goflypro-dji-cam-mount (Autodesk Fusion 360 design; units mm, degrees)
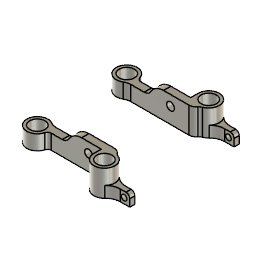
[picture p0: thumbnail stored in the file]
sketch "Skizze1" plane through (0, 0, 0) normal (0, 0, 1) x axis (1, 0, 0)
  line L1 (10, 0.85) -> (10, 2)
  line L2 (7.15, 0) -> (7.15, -2)
  line L3 (10, 2) -> (-7.9696, 2)
  line L4 (7.15, 0) -> (-7.15, 0)
  line L5 (-2, 0) -> (-2, 2)
  line L6 (8.5482, 0) -> (7.15, 0)
  line L7 (9.55, 0) -> (8.5482, 0)
  line L8 (10, 0.85) -> (10, 0.05)
  circle C1 centre (-10, 0) radius 2.05
  circle C2 centre (10, -2) radius 2.05
  circle C3 centre (-10, 0) radius 2.85
  circle C4 centre (10, -2) radius 2.85
  point P6 (7.15, -2)
  point P7 (10, 0.85)
  point P8 (-7.15, 0)
  point P9 (-7.9696, 2)
  point P12 (-2, 2)
  point P13 (-2, 0)
  point P15 (9.55, 0)
  point P16 (10, 0.05)
  concentric C1 C3
  coincident C4 P6
  tangent C4 L2
  coincident C4 P7
  perpendicular L1 L3
  perpendicular L2 L4
  coincident C3 P8
  coincident C3 P9
  coincident L3 P12
  coincident L4 P13
  perpendicular L4 L5
  perpendicular L2 L6
  parallel L6 L7
  perpendicular L7 L8
  coincident C2 P15
  coincident C2 P16
  dimension "d1" diameter C1 = 4.1
  dimension "d2" diameter C2 = 4.1
  dimension "d87" diameter C3 = 5.7
  dimension "d88" diameter C4 = 5.7
extrude "Extrusion1" new body sketch "Skizze1" profile of C2 L1 C4 L3 L4 L5 L6 L7 L8 along normal blind 7
extrude "Extrusion5" new body sketch "Skizze1" profile of C1 C3 L3 L4 L5 along normal blind 4 bodies "GoFlyPro - DJI - cam mount - left"
combine "Kombinieren"
sketch "Skizze2" plane through (0, 0, 0) normal (0, 1, 0) x axis (1, 0, 0)
  line L1 (7.2, 0) -> (1, 0)
  line L2 (7.2, -7) -> (7.2, 0)
  line L3 (1, -7) -> (7.2, -7)
  line L4 (1, 0) -> (1, -7)
  line L5 (7.15, 0) -> (-7.1942, 0)
  line L6 (-7.1942, -3) -> (-2, -3)
  line L7 (-2, -13) -> (7.15, -13)
  line L8 (-2, -3) -> (-2, -13)
  line L9 (-7.1942, 0) -> (-7.1942, -3)
  line L10 (7.15, -13) -> (7.15, 0)
  line L11 (9.55, 0) -> (-7.15, 0)
  line L12 (-2, -7) -> (9.55, -7)
  line L13 (-2, -4) -> (-2, -7)
  line L14 (-7.15, -4) -> (-2, -4)
  line L15 (-7.15, 0) -> (-7.15, -4)
  line L16 (9.55, -7) -> (9.55, 0)
  circle C1 centre (3.75, -4.25) radius 1.05
  circle C2 centre (8.3463, -8.1067) radius 1.05
  circle C3 centre (3.75, -4.25) radius 4.95
  circle C4 centre (3.75, -4.25) radius 7.05
  circle C5 centre (3.75, -10.25) radius 1.05
  concentric C1 C3
  tangent C2 C3
  concentric C3 C4
  tangent C2 C4
  dimension "d8" diameter C1 = 2.1
  dimension "d31" diameter C2 = 2.1
  dimension "d32" diameter C5 = 2.1
extrude "Extrusion2" cut sketch "Skizze2" profile of C1 along normal blind 2
fillet "Abrundung13" radius 1
fillet "Abrundung17" radius 4
fillet "Abrundung18" radius 2
fillet "Abrundung19" radius 3
sketch "Skizze3" plane through (0, 0, 0) normal (0, 0, 1) x axis (1, 0, 0)
  line L1 (12.5, -2.7) -> (17.5, -2.7)
  line L2 (12.5, -1.3) -> (12.5, -2.7)
  line L3 (17.5, -1.3) -> (12.5, -1.3)
  line L4 (17.5, -2.7) -> (17.5, -1.3)
  horizontal L1
  vertical L2
  horizontal L3
  vertical L4
extrude "Extrusion8" add sketch "Skizze3" along normal blind 3
extrude "Extrusion10" add sketch "Skizze1" profile of C2 C4 L2 L6 along normal blind 7
sketch "Skizze4" plane through (0, -2.7, 0) normal (0, -1, 0) x axis (1, 0, 0)
  line L1 (17.5, 0) -> (12.7627, 0)
  line L2 (17.5, 3) -> (17.5, 0)
  line L3 (12.7627, 3) -> (17.5, 3)
  line L4 (12.7627, 0) -> (12.7627, 3)
  circle C1 centre (16, 1.5) radius 0.75
  dimension "d82" diameter C1 = 1.5
extrude "Extrusion9" cut sketch "Skizze4" profile of C1 against normal blind 2
fillet "Abrundung20" radius 1
fillet "Abrundung21" radius 1.5
fillet "Abrundung23" radius 4
fillet "Abrundung25" radius 2
work_plane "Arbeitsebene" AlongDistance 12
mirror "Spiegeln" mirrorStitchTolerance 0.1 bodies "GoFlyPro - DJI - cam mount - right"
named bodies: "GoFlyPro - DJI - cam mount - left", "GoFlyPro - DJI - cam mount - right"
